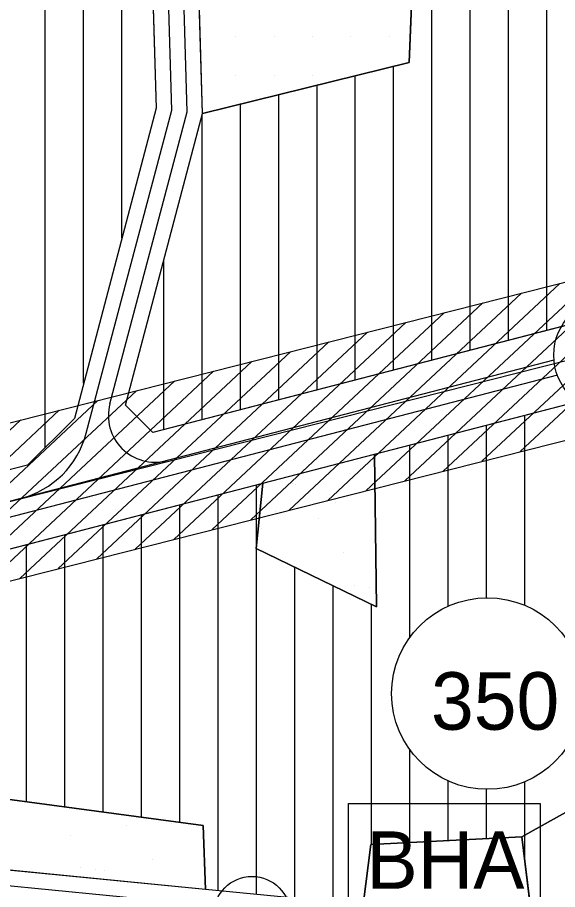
# Model space of a CAD drawing. Extents: x 419109 to 421295, y 4452223 to 4457798.
# Drawn here: x 419533.6 to 419674.5, y 4452503.6 to 4452731.2 of the extents above; entities that cross this region are included whole.
import ezdxf

# ---------------------------------------------------------------- set-up
doc = ezdxf.new("R2010")
doc.units = 0
for name, color, linetype in [('ADA', 7, 'Continuous'), ('ADAKENARI', 7, 'Continuous'), ('Default', 7, 'Continuous'), ('KALDIRIM', 7, 'Continuous'), ('KD_DAIRE', 7, 'Continuous'), ('LJ_SEMBOL', 7, 'Continuous'), ('PL_AYA_PARK_DINLENME', 7, 'Continuous'), ('PL_K_BHA', 7, 'Continuous'), ('PL_KON_MEV_350', 7, 'Continuous'), ('PL_SAY_DINI_TESIS', 7, 'Continuous'), ('SM_DAIRE', 7, 'Continuous'), ('SM_TAKS', 7, 'Continuous'), ('TA_ENH_154', 7, 'Continuous'), ('TA_ENH_KORUMA', 7, 'Continuous'), ('TA_ENH_TARAMA', 7, 'Continuous'), ('TR_DINITESIS', 7, 'Continuous'), ('TR_ORTAYOGUNKONUT', 7, 'Continuous'), ('TR_PARKALANI', 7, 'Continuous')]:
    doc.layers.add(name, color=color, linetype=linetype)

# ---------------------------------------------------------------- blocks, each defined once
blk = doc.blocks.new('POINT_DISPLAY')
at = {"layer": 'Default'}
blk.add_line((0, 0), (0, 0), dxfattribs=at)

msp = doc.modelspace()

# ---------------------------------------------------------------- linework, layer by layer
at = {"layer": 'ADA'}
for p, q in [((419637.41, 4452760.32), (419635.79, 4452719.45)), ((419635.79, 4452719.45), (419581.87, 4452706.08)), ((419627.31, 4452577.3), (419626.74, 4452617.16)), ((419597.6, 4452609.61), (419595.84, 4452592.54)), ((419595.84, 4452592.54), (419627.31, 4452577.3)), ((419530.93, 4452527.14), (419582.07, 4452520.26)), ((419582.07, 4452520.26), (419582.69, 4452503.57)), ((419625.83, 4452515.34), (419665.17, 4452517.31)), ((419665.17, 4452517.31), (419667.93, 4452495.21)), ((419623.77, 4452499.54), (419625.83, 4452515.34))]:
    msp.add_line(p, q, dxfattribs=at)
at = {"layer": 'ADAKENARI'}
for p, q in [((419567.02, 4452800.8), (419569.82, 4452707.46)), ((419581.87, 4452706.08), (419580.56, 4452749.66)), ((419569.82, 4452707.46), (419548.43, 4452626.52)), ((419561.75, 4452629.97), (419581.87, 4452706.08)), ((419775.98, 4452676.54), (419568.88, 4452622.82)), ((419626.74, 4452617.16), (419747.04, 4452648.37)), ((419568.88, 4452622.82), (419561.75, 4452629.97)), ((419548.43, 4452626.52), (419536.19, 4452614.34)), ((419597.6, 4452609.61), (419626.74, 4452617.16)), ((419536.19, 4452614.34), (419510.85, 4452607.76)), ((419515.87, 4452588.4), (419597.6, 4452609.61)), ((419582.69, 4452503.57), (419524.44, 4452509.29)), ((419623.77, 4452499.54), (419582.69, 4452503.57))]:
    msp.add_line(p, q, dxfattribs=at)
at = {"layer": 'KALDIRIM'}
for p, q in [((419573.84, 4452707), (419571.57, 4452782.68)), ((419577.86, 4452706.54), (419575.55, 4452783.19)), ((419551.53, 4452622.63), (419573.84, 4452707)), ((419557.71, 4452630.33), (419577.86, 4452706.54)), ((419673.58, 4452641.71), (419534.45, 4452605.62)), ((419674.46, 4452637.81), (419513.87, 4452596.15)), ((419534.45, 4452605.62), (419512.86, 4452600.02)), ((419514.95, 4452506.2), (419585.06, 4452499.32))]:
    msp.add_line(p, q, dxfattribs=at)
for centre, radius, start, end in [((419569.44, 4452627.23), 12.13, 165.1921, 284.5422), ((419528.46, 4452628.73), 23.87, 284.5422, 345.1921)]:
    msp.add_arc(centre, radius, start, end, dxfattribs=at)
at = {"layer": 'KD_DAIRE'}
for centre, radius in [((419688.52, 4452643.02), 15), ((419594.78, 4452496.97), 10)]:
    msp.add_circle(centre, radius, dxfattribs=at)
at = {"layer": 'LJ_SEMBOL'}
msp.add_lwpolyline([(419619.95, 4452526.05), (419669.95, 4452526.05), (419669.95, 4452496.05), (419619.95, 4452496.05), (419619.95, 4452526.05), (419669.95, 4452526.05)], dxfattribs=at)
at = {"layer": 'PL_AYA_PARK_DINLENME'}
for points in [[(419595.84, 4452592.54), (419597.6, 4452609.61), (419626.74, 4452617.16), (419627.31, 4452577.3)], [(419582.07, 4452520.26), (419582.69, 4452503.57), (419524.44, 4452509.29), (419530.93, 4452527.14)]]:
    msp.add_lwpolyline(points, close=True, dxfattribs=at)
at = {"layer": 'PL_K_BHA'}
msp.add_lwpolyline([(419625.83, 4452515.34), (419665.17, 4452517.31), (419667.93, 4452495.21), (419623.77, 4452499.54)], close=True, dxfattribs=at)
at = {"layer": 'PL_KON_MEV_350'}
msp.add_lwpolyline([(419796.33, 4452996.11), (419805.41, 4452988.48), (419786.29, 4452689.03), (419775.98, 4452676.54), (419568.88, 4452622.82), (419561.75, 4452629.97), (419581.87, 4452706.08), (419635.79, 4452719.45), (419637.41, 4452760.32), (419700.32, 4452851.73), (419754.09, 4452844.74), (419741.18, 4452876.46), (419703.54, 4452885.61), (419700.32, 4452851.73), (419637.41, 4452760.32), (419580.56, 4452749.66), (419577.39, 4452855.4), (419570.34, 4452931.11), (419579.14, 4452943.43)], close=True, dxfattribs=at)
for points in [[(419567.02, 4452800.8), (419569.82, 4452707.46), (419548.43, 4452626.52), (419536.19, 4452614.34), (419510.85, 4452607.76), (419504.63, 4452606.36), (419498.33, 4452605.36), (419491.98, 4452604.75), (419485.61, 4452604.56), (419479.24, 4452604.77), (419472.89, 4452605.39), (419466.59, 4452606.41), (419460.38, 4452607.83), (419454.26, 4452609.64), (419448.28, 4452611.84), (419442.44, 4452614.42), (419436.79, 4452617.36), (419431.33, 4452620.66), (419314.74, 4452696.28), (419310.85, 4452710.65), (419356.12, 4452800.45)], [(419388.24, 4452493.2), (419339.7, 4452521.65), (419335.95, 4452535.44), (419341.29, 4452545), (419357.85, 4452536.98), (419367.19, 4452550.25), (419515.87, 4452588.4), (419597.6, 4452609.61), (419595.84, 4452592.54), (419627.31, 4452577.3), (419626.74, 4452617.16), (419747.04, 4452648.37)], [(419707.45, 4452540.91), (419665.17, 4452517.31), (419625.83, 4452515.34), (419623.77, 4452499.54), (419582.69, 4452503.57), (419582.07, 4452520.26), (419530.93, 4452527.14), (419524.44, 4452509.29), (419515.34, 4452510.18), (419511.52, 4452510.35), (419507.71, 4452510.14), (419503.95, 4452509.53), (419500.26, 4452508.54), (419496.7, 4452507.17), (419493.3, 4452505.44), (419490.09, 4452503.37)], [(419705.11, 4452491.56), (419667.93, 4452495.21), (419665.17, 4452517.31), (419707.45, 4452540.91)]]:
    msp.add_lwpolyline(points, dxfattribs=at)
at = {"layer": 'PL_SAY_DINI_TESIS'}
msp.add_lwpolyline([(419580.56, 4452749.66), (419637.41, 4452760.32), (419635.79, 4452719.45), (419581.87, 4452706.08)], close=True, dxfattribs=at)
at = {"layer": 'SM_DAIRE'}
msp.add_circle((419656.23, 4452554.71), 25, dxfattribs=at)
at = {"layer": 'TA_ENH_154'}
msp.add_lwpolyline([(421244.23, 4452871.73), (420603.45, 4452866.93), (420104.11, 4452747.15), (419709.07, 4452649.72), (419353.3, 4452559.56), (419284.53, 4452601.29), (419287.68, 4452599.87), (419484.08, 4452691.72), (419833.95, 4454863.94), (419862.83, 4455014.24)], dxfattribs=at)
at = {"layer": 'TA_ENH_KORUMA'}
msp.add_lwpolyline([(419883.15, 4455014.02), (419853.65, 4454860.46), (419502.14, 4452678.09), (419329.55, 4452597.37), (419356.51, 4452581.01), (419704.22, 4452669.12), (420099.38, 4452766.58), (420601.01, 4452886.92), (421244.44, 4452891.74)], dxfattribs=at)
at = {"layer": 'TA_ENH_TARAMA'}
for p, q in [((419664.79, 4452617.86), (419725.17, 4452674.29)), ((419654.74, 4452615.32), (419715.22, 4452671.84)), ((419644.69, 4452612.77), (419705.27, 4452669.38)), ((419634.65, 4452610.23), (419695.23, 4452666.85)), ((419624.6, 4452607.68), (419685.18, 4452664.3)), ((419614.55, 4452605.13), (419675.13, 4452661.75)), ((419604.5, 4452602.59), (419665.09, 4452659.21)), ((419594.45, 4452600.04), (419655.04, 4452656.66)), ((419584.41, 4452597.49), (419644.99, 4452654.12)), ((419574.36, 4452594.95), (419634.94, 4452651.57)), ((419564.31, 4452592.4), (419624.89, 4452649.02)), ((419554.26, 4452589.86), (419614.85, 4452646.48)), ((419544.21, 4452587.31), (419604.8, 4452643.93)), ((419534.17, 4452584.76), (419594.75, 4452641.38)), ((419524.12, 4452582.22), (419584.7, 4452638.84)), ((419514.07, 4452579.67), (419574.65, 4452636.29)), ((419504.02, 4452577.13), (419564.61, 4452633.75)), ((419350.09, 4452538.12), (419713.92, 4452630.31)), ((419493.97, 4452574.58), (419554.56, 4452631.2)), ((419483.93, 4452572.03), (419544.51, 4452628.65)), ((419473.88, 4452569.49), (419534.46, 4452626.11))]:
    msp.add_line(p, q, dxfattribs=at)
at = {"layer": 'TR_ORTAYOGUNKONUT'}
for p, q in [((419671.75, 4452649.5), (419671.75, 4452965.89)), ((419661.75, 4452646.91), (419661.75, 4452867.54)), ((419651.75, 4452644.31), (419651.75, 4452860.16)), ((419641.75, 4452641.72), (419641.75, 4452858.34)), ((419540.85, 4452618.98), (419540.85, 4452799.01)), ((419550.85, 4452635.7), (419550.85, 4452799.69)), ((419560.85, 4452673.53), (419560.85, 4452800.38)), ((419631.75, 4452639.13), (419631.75, 4452718.45)), ((419621.75, 4452636.53), (419621.75, 4452715.97)), ((419611.75, 4452633.94), (419611.75, 4452713.49)), ((419601.75, 4452631.34), (419601.75, 4452711.01)), ((419591.75, 4452628.75), (419591.75, 4452708.53)), ((419581.75, 4452626.16), (419581.75, 4452705.63)), ((419571.75, 4452623.56), (419571.75, 4452667.8)), ((419665.95, 4452577.75), (419665.95, 4452627.33)), ((419655.95, 4452579.71), (419655.95, 4452624.74)), ((419645.95, 4452577.5), (419645.95, 4452622.15)), ((419635.95, 4452569.33), (419635.95, 4452619.55)), ((419595.95, 4452593.64), (419595.95, 4452609.18)), ((419585.95, 4452503.25), (419585.95, 4452606.58)), ((419575.95, 4452521.08), (419575.95, 4452603.99)), ((419565.95, 4452522.43), (419565.95, 4452601.39)), ((419555.95, 4452523.77), (419555.95, 4452598.8)), ((419545.95, 4452525.12), (419545.95, 4452596.21)), ((419535.95, 4452526.47), (419535.95, 4452593.61)), ((419595.95, 4452502.27), (419595.95, 4452592.48)), ((419605.95, 4452501.29), (419605.95, 4452587.64)), ((419615.95, 4452500.31), (419615.95, 4452582.8)), ((419625.95, 4452515.35), (419625.95, 4452577.95)), ((419635.95, 4452515.85), (419635.95, 4452540.09)), ((419645.95, 4452516.35), (419645.95, 4452531.92)), ((419655.95, 4452516.85), (419655.95, 4452529.71)), ((419665.95, 4452511.04), (419665.95, 4452531.68))]:
    msp.add_line(p, q, dxfattribs=at)

# ---------------------------------------------------------------- block references
at = {"layer": 'TR_DINITESIS', "xscale": 0.1, "yscale": 0.10000000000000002}
for p in [(419590.56, 4452726.08), (419600.56, 4452726.08), (419610.56, 4452726.08), (419620.56, 4452726.08), (419630.56, 4452726.08), (419590.56, 4452716.08), (419600.56, 4452716.08), (419610.56, 4452716.08), (419620.56, 4452716.08)]:
    msp.add_blockref('POINT_DISPLAY', p, dxfattribs=at)
at = {"layer": 'TR_PARKALANI', "xscale": 0.1, "yscale": 0.10000000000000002}
for p in [(419620.17, 4452612.05), (419605.4, 4452609.44), (419606.04, 4452609.17), (419616.48, 4452604.62), (419626.83, 4452603.07), (419600.84, 4452602.3), (419612.06, 4452600.46), (419597.29, 4452597.86), (419618.72, 4452591.49), (419603.95, 4452588.88), (419621.49, 4452582.97), (419625.38, 4452582.51), (419558.98, 4452523.36), (419573.75, 4452520.76), (419562.09, 4452520.37), (419547.32, 4452517.76), (419550.09, 4452509.25), (419568.75, 4452511.39), (419553.98, 4452508.78), (419556.38, 4452508.59)]:
    msp.add_blockref('POINT_DISPLAY', p, dxfattribs=at)

# ---------------------------------------------------------------- texts
at = {"layer": 'LJ_SEMBOL'}
msp.add_text('BHA', height=15, dxfattribs=at).set_placement((419624.65, 4452503.74))
at = {"layer": 'SM_TAKS'}
msp.add_text('350', height=15, dxfattribs=at).set_placement((419641.49, 4452545.27))

doc.saveas('drawing.dxf')
